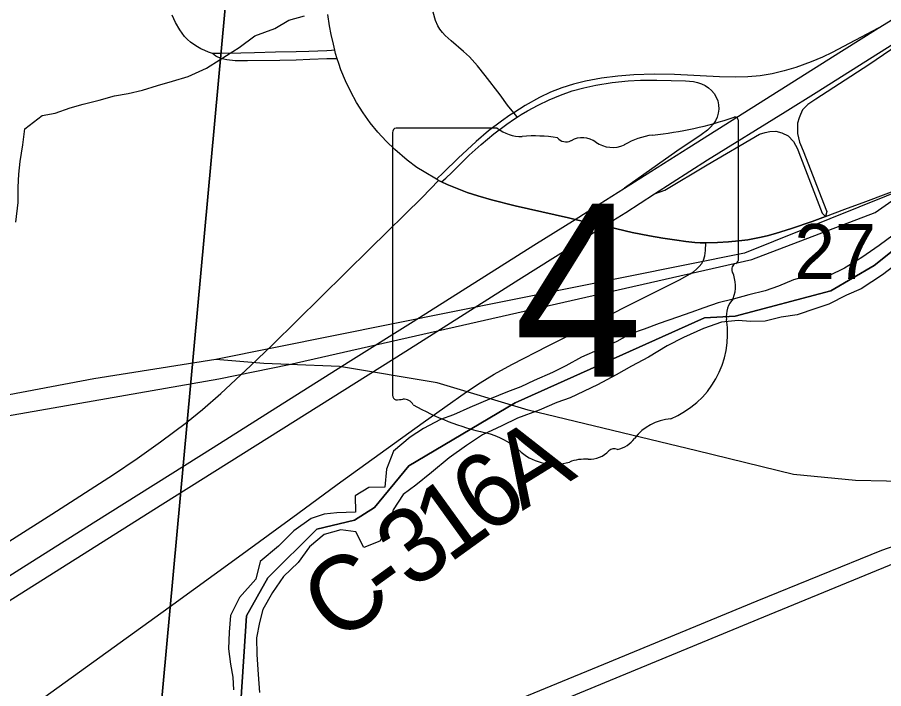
# Model space of a CAD drawing. Extents: x 831 to 1552, y 430 to 870.
# Drawn here: x 1344.04 to 1357.25, y 702.9 to 713.13 of the extents above; entities that cross this region are included whole.
import ezdxf

# ---------------------------------------------------------------- set-up
doc = ezdxf.new("R2010")
doc.units = 0
for name, color, linetype in [('GM_X_Corporation', 7, 'Continuous'), ('GM_X_County_Road', 7, 'Continuous'), ('GM_X_County_Road_Text', 7, 'Continuous'), ('GM_X_Interchange_Ramps', 7, 'Continuous'), ('GM_X_Major_River', 7, 'Continuous'), ('GM_X_Minor_River', 7, 'Continuous'), ('GM_X_Rail_Line', 7, 'Continuous'), ('GM_X_Section_Text', 7, 'Continuous'), ('GM_X_State_Location', 7, 'Continuous'), ('GM_X_State_Route', 7, 'Continuous'), ('GM_X_State_Shield', 7, 'Continuous'), ('GM_X_Township_Road', 7, 'Continuous')]:
    doc.layers.add(name, color=color, linetype=linetype)

msp = doc.modelspace()

# ---------------------------------------------------------------- linework, layer by layer
at = {"layer": 'GM_X_Corporation'}
for points in [[(1327.468, 722.912), (1347.89, 720.702), (1346.049, 700.645), (1325.539, 702.531)], [(1347.89, 720.702), (1366.951, 719.126), (1365.244, 698.931), (1346.049, 700.645)]]:
    msp.add_lwpolyline(points, close=True, dxfattribs=at)
for points in [[(1364.039, 710.393), (1363.434, 710.53), (1362.141, 710.75), (1361.04, 710.888), (1360.16, 710.86), (1359.555, 710.778), (1358.509, 710.31), (1357.657, 709.787), (1357.106, 709.347), (1356.446, 708.962), (1354.988, 708.577), (1354.52, 708.549), (1351.632, 707.256), (1350.009, 706.294), (1349.486, 705.661), (1349.183, 705.468), (1348.606, 705.331), (1347.863, 704.588), (1347.533, 704.01), (1347.45, 702.69)], [(1347.45, 702.69), (1347.533, 704.01), (1347.863, 704.588), (1348.606, 705.331), (1349.183, 705.468), (1349.486, 705.661), (1350.009, 706.294), (1351.632, 707.256), (1354.52, 708.549), (1354.988, 708.577), (1356.446, 708.962), (1357.106, 709.347), (1357.657, 709.787), (1358.509, 710.31), (1359.555, 710.778), (1360.16, 710.86), (1361.04, 710.888), (1362.141, 710.75), (1363.434, 710.53), (1364.039, 710.393)]]:
    msp.add_lwpolyline(points, dxfattribs=at)
at = {"layer": 'GM_X_County_Road'}
msp.add_line((1350.462, 710.645), (1350.508, 710.623), dxfattribs=at)
for points in [[(1340.029, 702.639), (1340.863, 703.18), (1342.12, 703.983), (1342.713, 704.369), (1343.362, 704.795), (1344.569, 705.559), (1345.509, 706.164), (1345.869, 706.407), (1346.224, 706.659), (1346.621, 706.957), (1346.863, 707.151), (1347.142, 707.396), (1347.599, 707.817), (1347.931, 708.141), (1349.418, 709.601), (1350.216, 710.385), (1350.462, 710.645)], [(1350.508, 710.623), (1350.597, 710.583), (1350.747, 710.519), (1350.901, 710.462), (1351.065, 710.41), (1351.273, 710.351), (1351.632, 710.259), (1352.445, 710.074), (1352.545, 710.051), (1352.762, 710), (1352.987, 709.95), (1353.121, 709.92), (1353.18, 709.907)], [(1356.365, 710.097), (1356.659, 710.205), (1356.977, 710.325), (1357.559, 710.543)], [(1354.54, 709.692), (1354.717, 709.697), (1354.885, 709.707), (1355.042, 709.722), (1355.181, 709.741), (1355.357, 709.774), (1355.474, 709.801), (1355.6, 709.835), (1355.847, 709.91), (1356.162, 710.02), (1356.365, 710.097)], [(1353.18, 709.907), (1353.414, 709.853), (1353.678, 709.801), (1353.885, 709.766), (1354.095, 709.734), (1354.234, 709.715), (1354.373, 709.7), (1354.455, 709.695), (1354.54, 709.692)], [(1344.242, 702.614), (1346.358, 704.142), (1347.414, 704.909), (1348.318, 705.568), (1348.92, 706.009), (1350.231, 706.954), (1350.889, 707.423), (1351.097, 707.561), (1351.31, 707.69), (1351.583, 707.84), (1352.137, 708.123), (1353.58, 708.852), (1354.136, 709.129), (1354.298, 709.219), (1354.349, 709.253), (1354.396, 709.29), (1354.439, 709.331), (1354.476, 709.377), (1354.503, 709.428), (1354.523, 709.494), (1354.533, 709.576), (1354.54, 709.692)]]:
    msp.add_lwpolyline(points, dxfattribs=at)
at = {"layer": 'GM_X_Interchange_Ramps'}
for points in [[(1357.165, 712.965), (1356.466, 712.595), (1356.317, 712.523), (1356.146, 712.451), (1355.912, 712.366), (1355.733, 712.313), (1355.552, 712.271), (1355.368, 712.241), (1355.182, 712.223), (1354.996, 712.217), (1354.747, 712.222), (1354.064, 712.26), (1353.754, 712.265), (1353.443, 712.255), (1353.195, 712.236), (1352.948, 712.204), (1352.704, 712.158), (1352.523, 712.113), (1352.345, 712.057), (1352.172, 711.988), (1352.004, 711.908), (1351.786, 711.787), (1351.611, 711.677), (1351.549, 711.637), (1351.422, 711.55), (1351.225, 711.398), (1351.037, 711.237), (1350.762, 710.984), (1350.54, 710.767), (1350.433, 710.662)], [(1350.508, 710.623), (1350.573, 710.681), (1350.666, 710.764), (1350.931, 711.027), (1351.115, 711.194), (1351.306, 711.354), (1351.505, 711.504), (1351.621, 711.582), (1351.665, 711.611), (1351.721, 711.647), (1351.819, 711.705), (1351.984, 711.794), (1352.153, 711.874), (1352.325, 711.946), (1352.501, 712.009), (1352.681, 712.058), (1352.863, 712.097), (1353.109, 712.137), (1353.357, 712.164), (1353.543, 712.174), (1353.792, 712.175), (1354.229, 712.163), (1354.353, 712.15), (1354.414, 712.137), (1354.473, 712.118), (1354.529, 712.092), (1354.581, 712.057), (1354.627, 712.016), (1354.666, 711.968), (1354.698, 711.914), (1354.72, 711.856), (1354.733, 711.795), (1354.736, 711.733), (1354.728, 711.671), (1354.712, 711.611), (1354.687, 711.554), (1354.653, 711.502), (1354.612, 711.455), (1354.566, 711.413), (1354.467, 711.337), (1354.099, 711.089), (1353.297, 710.524)]]:
    msp.add_lwpolyline(points, dxfattribs=at)
at = {"layer": 'GM_X_Major_River'}
for points in [[(1357.396, 709.81), (1357.18, 709.655), (1356.917, 709.471), (1356.655, 709.309), (1356.416, 709.192), (1356.15, 709.206), (1355.875, 709.128), (1355.645, 709.034), (1355.445, 708.963), (1355.193, 708.9), (1354.956, 708.837), (1354.726, 708.781), (1354.511, 708.702), (1354.312, 708.63), (1354.105, 708.559), (1353.829, 708.466), (1353.599, 708.38), (1353.392, 708.308), (1353.184, 708.191), (1352.923, 708.075), (1352.646, 707.952), (1352.407, 707.82), (1352.2, 707.718), (1351.923, 707.595), (1351.716, 707.501), (1351.516, 707.421), (1351.24, 707.313), (1350.94, 707.183), (1350.694, 707.074), (1350.495, 707.002), (1350.233, 706.864), (1350.033, 706.731), (1349.777, 706.516), (1349.672, 706.245), (1349.643, 705.971), (1349.399, 705.962), (1349.191, 705.837), (1349.2, 705.586), (1348.911, 705.577), (1348.721, 705.558), (1348.521, 705.494), (1348.259, 705.302), (1348.025, 705.071), (1347.746, 704.834), (1347.679, 704.569), (1347.429, 704.286), (1347.294, 704.015), (1347.273, 703.757), (1347.26, 703.506), (1347.292, 703.27), (1347.326, 703.071), (1347.337, 702.881)], [(1357.424, 709.353), (1357.231, 709.205), (1356.906, 708.992), (1356.684, 708.898), (1356.414, 708.759), (1356.215, 708.695), (1355.931, 708.595), (1355.687, 708.562), (1355.442, 708.499), (1355.222, 708.496), (1355.032, 708.508), (1354.78, 708.483), (1354.504, 708.39), (1354.197, 708.252), (1353.951, 708.121), (1353.665, 707.952), (1353.404, 707.813), (1353.172, 707.681), (1352.888, 707.528), (1352.472, 707.332), (1352.265, 707.26), (1351.997, 707.144), (1351.667, 707.022), (1351.428, 706.906), (1351.136, 706.768), (1350.889, 706.606), (1350.626, 706.414), (1350.355, 706.192), (1350.115, 705.999), (1349.922, 705.859), (1349.772, 705.626), (1349.714, 705.407), (1349.571, 705.144), (1349.325, 705.05), (1349.201, 705.289), (1348.974, 705.317), (1348.721, 705.246), (1348.496, 705.061), (1348.324, 704.821), (1348.098, 704.606), (1347.933, 704.366), (1347.783, 704.103), (1347.733, 703.906), (1347.689, 703.672), (1347.691, 703.421), (1347.715, 703.116), (1347.732, 702.842)]]:
    msp.add_lwpolyline(points, dxfattribs=at)
at = {"layer": 'GM_X_Minor_River'}
msp.add_lwpolyline([(1344.018, 710.006), (1344.052, 710.309), (1344.055, 710.544), (1344.065, 710.742), (1344.083, 710.931), (1344.124, 711.189), (1344.157, 711.432), (1344.418, 711.634), (1344.616, 711.669), (1344.845, 711.75), (1345.043, 711.809), (1345.287, 711.866), (1345.523, 711.932), (1345.729, 711.967), (1345.95, 712.018), (1346.179, 712.091), (1346.407, 712.157), (1346.644, 712.23), (1346.926, 712.356), (1347.133, 712.49), (1347.424, 712.669), (1347.662, 712.848), (1347.967, 712.958), (1348.181, 713.085), (1348.418, 713.151)], dxfattribs=at)
at = {"layer": 'GM_X_Rail_Line'}
for points in [[(1357.73, 710.582), (1355.13, 709.534), (1347.068, 707.913)], [(1348.184, 707.837), (1355.243, 709.441), (1357.121, 710.156), (1357.73, 710.582)], [(1347.068, 707.913), (1345.209, 707.623), (1335.331, 705.755), (1325.651, 703.882), (1316.479, 702.146), (1309.906, 700.809), (1302.408, 699.333), (1299.88, 698.86), (1298.165, 698.538), (1295.52, 698.073)], [(1348.184, 707.837), (1347.802, 707.852), (1347.068, 707.913)], [(1250.766, 679.957), (1255.444, 683.813), (1257.495, 685.358), (1259.895, 687.02), (1261.608, 688.118), (1265.466, 690.461), (1268.571, 692.318), (1270.198, 693.26), (1277.176, 696.209), (1284.864, 698.305), (1290.582, 698.552), (1291.934, 698.299), (1293.404, 698.016), (1295.482, 697.897), (1297.508, 698.271), (1299.512, 698.644), (1302.371, 699.157), (1309.027, 700.546), (1335.38, 705.567), (1347.114, 707.619), (1348.184, 707.837)], [(1363.58, 707.737), (1361.736, 706.873), (1360.428, 706.418), (1358.901, 706.162), (1357.768, 706.05), (1356.822, 706.07), (1355.876, 706.162), (1354.403, 706.521), (1351.829, 707.144), (1350.444, 707.56), (1348.956, 707.806), (1348.184, 707.837)], [(1331.029, 690.356), (1334.139, 692.492), (1336.804, 694.323), (1342.617, 698.318), (1344.051, 699.217), (1345.113, 699.834), (1345.965, 700.291), (1346.839, 700.712), (1347.861, 701.155), (1350.4, 702.208), (1352.984, 703.272), (1355.322, 704.238), (1357.221, 705.009), (1357.803, 705.212), (1358.348, 705.377), (1359.339, 705.66), (1360.057, 705.898), (1360.633, 706.108), (1361.404, 706.431)], [(1324.617, 685.605), (1327.389, 687.515), (1329.015, 688.636), (1331.181, 690.137), (1334.291, 692.272), (1336.956, 694.104), (1342.764, 698.096), (1344.19, 698.989), (1345.244, 699.602), (1346.087, 700.054), (1346.951, 700.47), (1347.965, 700.91), (1350.503, 701.962), (1353.086, 703.026), (1355.423, 703.992), (1360.057, 705.898)]]:
    msp.add_lwpolyline(points, dxfattribs=at)
at = {"layer": 'GM_X_State_Route'}
msp.add_line((1350.508, 710.623), (1350.462, 710.645), dxfattribs=at)
for points in [[(1357.165, 712.965), (1357.324, 713.064), (1358.466, 713.785), (1359.485, 714.418), (1360.53, 715.085), (1361.949, 715.98), (1363.001, 716.643), (1364.105, 717.338), (1365.214, 718.025), (1366.924, 719.077), (1367.436, 719.392), (1369.287, 720.533), (1370.346, 721.183), (1371.298, 721.77), (1372.674, 722.617), (1376.115, 724.732), (1378.283, 726.071), (1380.083, 727.178), (1381.036, 727.763), (1382.148, 728.446), (1383.542, 729.306)], [(1350.462, 710.645), (1350.433, 710.662), (1350.245, 710.774), (1350.134, 710.844), (1349.986, 710.955), (1349.798, 711.116), (1349.664, 711.244), (1349.538, 711.38), (1349.422, 711.524), (1349.313, 711.675), (1349.214, 711.832), (1349.124, 711.994), (1349.044, 712.161), (1348.974, 712.332), (1348.941, 712.427), (1348.919, 712.5), (1348.895, 712.577), (1348.882, 712.631), (1348.86, 712.719), (1348.827, 712.868), (1348.802, 713), (1348.777, 713.174)], [(1333.187, 697.843), (1335.988, 699.621), (1336.934, 700.218), (1339.247, 701.676), (1342.98, 704.025), (1344.137, 704.754), (1345.24, 705.451), (1347.026, 706.576), (1348.077, 707.238), (1349.128, 707.902), (1350.076, 708.496), (1351.915, 709.656), (1352.545, 710.051), (1352.915, 710.283), (1353.297, 710.524), (1353.703, 710.78), (1354.282, 711.144), (1356.61, 712.615), (1357.165, 712.965)], [(1353.758, 710.44), (1354.564, 710.96), (1355.747, 711.692), (1356.22, 711.985), (1357.698, 712.915)], [(1357.698, 712.915), (1357.582, 712.788), (1357.027, 712.407), (1356.214, 711.881), (1356.093, 711.802), (1356.014, 711.719), (1355.981, 711.65), (1355.961, 711.598), (1355.938, 711.519), (1355.935, 711.44), (1355.935, 711.361), (1355.968, 711.229), (1355.998, 711.156), (1356.033, 711.072), (1356.371, 710.207)], [(1353.758, 710.44), (1353.915, 710.494), (1354.559, 710.881), (1355.357, 711.349), (1355.443, 711.377), (1355.515, 711.391), (1355.608, 711.397), (1355.697, 711.369), (1355.794, 711.323), (1355.875, 711.237), (1355.938, 711.125), (1355.959, 711.072), (1356.312, 710.146), (1356.365, 710.097)], [(1353.18, 709.907), (1353.121, 709.92), (1352.987, 709.95), (1352.762, 710), (1352.545, 710.051), (1352.445, 710.074), (1351.632, 710.259), (1351.273, 710.351), (1351.065, 710.41), (1350.901, 710.462), (1350.747, 710.519), (1350.597, 710.583), (1350.508, 710.623)], [(1352.765, 709.811), (1352.987, 709.95), (1353.319, 710.158), (1353.758, 710.44)], [(1356.371, 710.207), (1356.386, 710.17), (1356.365, 710.097)], [(1356.365, 710.097), (1356.162, 710.02), (1355.847, 709.91), (1355.6, 709.835), (1355.474, 709.801), (1355.357, 709.774), (1355.181, 709.741), (1355.042, 709.722), (1354.885, 709.707), (1354.717, 709.697), (1354.54, 709.692)], [(1354.54, 709.692), (1354.455, 709.695), (1354.373, 709.7), (1354.234, 709.715), (1354.095, 709.734), (1353.885, 709.766), (1353.678, 709.801), (1353.414, 709.853), (1353.18, 709.907)], [(1327.572, 693.951), (1327.781, 694.084), (1329.474, 695.148), (1330.997, 696.104), (1332.731, 697.181), (1334.273, 698.15), (1336.026, 699.258), (1337.813, 700.381), (1339.619, 701.524), (1340.853, 702.296), (1342.496, 703.341), (1344.305, 704.48), (1346.259, 705.713), (1348.062, 706.849), (1349.964, 708.043), (1351.69, 709.137), (1352.765, 709.811)]]:
    msp.add_lwpolyline(points, dxfattribs=at)
at = {"layer": 'GM_X_State_Shield'}
for p, q in [((1355.037, 709.448), (1355.037, 711.542)), ((1349.764, 711.374), (1349.764, 707.371)), ((1351.36, 711.443), (1349.816, 711.443)), ((1355.037, 709.449), (1355.037, 709.448))]:
    msp.add_line(p, q, dxfattribs=at)
for centre, radius, start, end in [((1353.159, 716.899), 5.592, 275.8445, 288.9065), ((1354.979, 711.551), 0.0587, 351.8621, 97.738), ((1349.824, 711.382), 0.0611, 98.1301, 188.1301), ((1351.728, 711.907), 0.593, 231.6195, 271.1119), ((1351.924, 709.196), 2.127, 80.4867, 94.9883), ((1352.407, 711.403), 0.171, 219.7921, 297.1024), ((1352.658, 710.94), 0.355, 54.4667, 119.1411), ((1353.117, 711.575), 0.428, 233.8562, 294.8282), ((1353.872, 710.22), 1.125, 97.3462, 120.7689), ((1355.024, 709.294), 0.0909, 107.944, 210.337), ((1354.975, 709.44), 0.0628, 289.6038, 7.7341), ((1354.446, 709.03), 0.545, 340.033, 23.6496), ((1355.248, 708.572), 0.397, 136.8065, 186.9296), ((1353.472, 708.306), 1.399, 292.3089, 8.9858), ((1349.825, 707.363), 0.0616, 171.9584, 258.3066), ((1349.834, 707.772), 0.47, 267.339, 280.6039), ((1349.93, 707.141), 0.17, 29.7484, 93.2717), ((1352.072, 710.736), 4.038, 240.4129, 257.1985), ((1354.062, 706.248), 0.766, 94.4031, 142.5768), ((1350.868, 705.573), 1.264, 47.1842, 75.836), ((1353.091, 706.983), 0.452, 282.8732, 323.2771), ((1352.234, 707.121), 0.802, 230.7004, 286.2918), ((1352.756, 706.821), 0.427, 268.777, 315.5493), ((1353.142, 706.433), 0.12, 65.7517, 132.6484), ((1352.697, 705.737), 0.659, 85.6951, 111.2099)]:
    msp.add_arc(centre, radius, start, end, dxfattribs=at)
at = {"layer": 'GM_X_Township_Road'}
for points in [[(1351.611, 711.677), (1351.517, 711.791), (1351.401, 711.95), (1351.176, 712.245), (1351.059, 712.389), (1350.934, 712.526), (1350.844, 712.611), (1350.655, 712.772), (1350.563, 712.855), (1350.522, 712.901), (1350.484, 712.949), (1350.455, 713.003), (1350.418, 713.082), (1350.382, 713.207)], [(1347.017, 712.581), (1346.957, 712.6), (1346.898, 712.623), (1346.841, 712.65), (1346.786, 712.681), (1346.734, 712.716), (1346.684, 712.752), (1346.635, 712.793), (1346.591, 712.84), (1346.518, 712.942), (1346.455, 713.049), (1346.427, 713.106), (1346.403, 713.164)], [(1348.882, 712.631), (1348.834, 712.627), (1348.758, 712.62), (1348.487, 712.61), (1348.294, 712.604), (1347.978, 712.599), (1347.655, 712.589), (1347.448, 712.582), (1347.145, 712.58), (1347.017, 712.581)], [(1348.919, 712.5), (1348.863, 712.499), (1348.76, 712.497), (1348.5, 712.487), (1348.292, 712.478), (1348.044, 712.474), (1347.549, 712.465), (1347.362, 712.468), (1347.238, 712.481), (1347.143, 712.504), (1347.07, 712.538), (1347.017, 712.581)], [(1351.665, 711.611), (1351.643, 711.638), (1351.611, 711.677)]]:
    msp.add_lwpolyline(points, dxfattribs=at)

# ---------------------------------------------------------------- texts
at = {"layer": 'GM_X_County_Road_Text'}
for s, rotation, p in [('A', 31.71, (1351.741, 705.604)), ('6', 35.7385, (1351.19, 705.207)), ('1', 35.8426, (1350.623, 704.797)), ('3', 35.8707, (1350.056, 704.387)), ('C', 35.8816, (1348.922, 703.567)), ('-', 35.8855, (1349.678, 704.114))]:
    msp.add_text(s, height=1.136, rotation=rotation, dxfattribs=at).set_placement(p)
at = {"layer": 'GM_X_Section_Text'}
msp.add_text('27', height=0.8371, rotation=0, dxfattribs=at).set_placement((1355.887, 709.143))
at = {"layer": 'GM_X_State_Location'}
for s in ['s', 'r']:
    msp.add_text(s, height=0.00379, dxfattribs=at).set_placement((1352.341, 709.107))
msp.add_text('4', height=0.00379, rotation=0, dxfattribs=at).set_placement((1351.771, 708.831))
at = {"layer": 'GM_X_State_Shield'}
msp.add_text('4', height=2.637, dxfattribs=at).set_placement((1351.617, 707.654))

doc.saveas('drawing.dxf')
